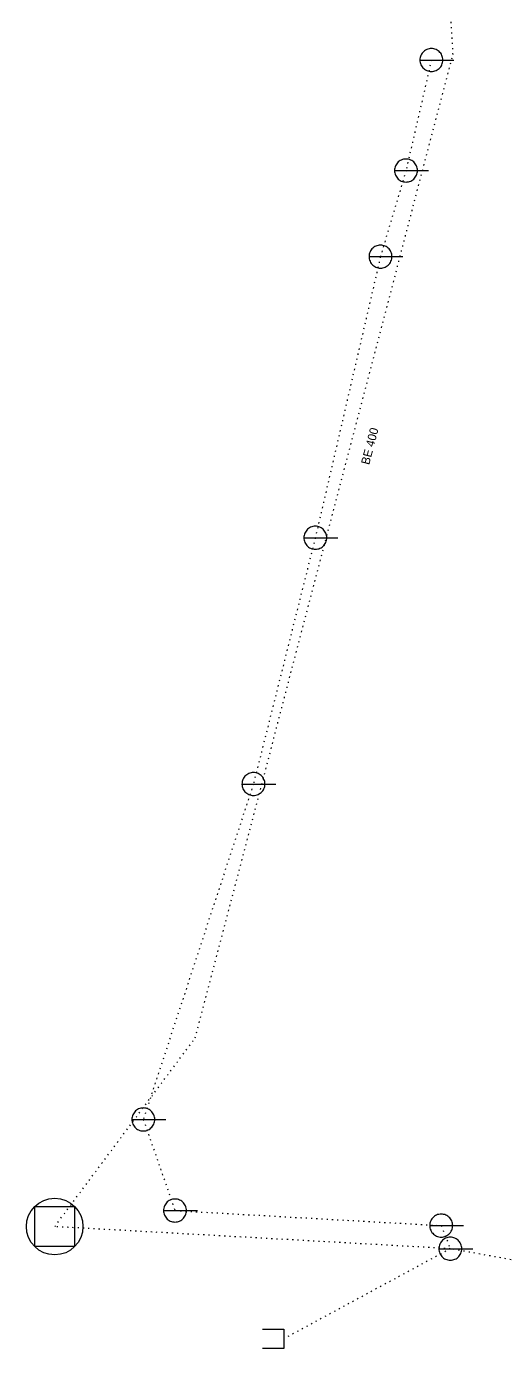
# Model space of a CAD drawing. Extents: x -688177 to -687620, y -1056713 to -1056287.
# Drawn here: x -688109.2 to -688067.1, y -1056697.7 to -1056581.7 of the extents above; entities that cross this region are included whole.
import ezdxf

# ---------------------------------------------------------------- set-up
doc = ezdxf.new("R2010")
doc.units = 0
doc.header["$LTSCALE"] = 0.3
doc.linetypes.add('DOTTED', pattern=[1.5, 0.3, -1.2])
for name, color, linetype, lineweight in [('12', 7, 'Continuous', 13), ('41', 7, 'DOTTED', 13), ('46', 7, 'DOTTED', 13)]:
    doc.layers.add(name, color=color, linetype=linetype, lineweight=lineweight)
doc.layers.add('18', color=7, linetype='Continuous')

msp = doc.modelspace()

# ---------------------------------------------------------------- linework, layer by layer
at = {"layer": '12'}
for p, q in [((-688074.648, -1056584.68), (-688071.672, -1056584.68)), ((-688076.878, -1056594.37), (-688073.902, -1056594.37)), ((-688079.118, -1056601.92), (-688076.142, -1056601.92)), ((-688084.838, -1056626.58), (-688081.862, -1056626.58)), ((-688090.268, -1056648.18), (-688087.292, -1056648.18)), ((-688099.938, -1056677.6), (-688096.962, -1056677.6)), ((-688097.158, -1056685.59), (-688094.182, -1056685.59)), ((-688073.788, -1056686.91), (-688070.812, -1056686.91)), ((-688072.988, -1056688.94), (-688070.012, -1056688.94)), ((-688086.607, -1056696.84), (-688086.593, -1056696.84))]:
    msp.add_line(p, q, dxfattribs=at)
for points in [[(-688073.64, -1056583.672), (-688073.745, -1056583.678), (-688073.849, -1056583.694), (-688073.951, -1056583.722), (-688074.05, -1056583.76), (-688074.144, -1056583.807), (-688074.232, -1056583.865), (-688074.314, -1056583.931), (-688074.389, -1056584.006), (-688074.455, -1056584.088), (-688074.513, -1056584.176), (-688074.56, -1056584.27), (-688074.598, -1056584.369), (-688074.626, -1056584.471), (-688074.642, -1056584.575), (-688074.648, -1056584.68), (-688074.642, -1056584.785), (-688074.626, -1056584.89), (-688074.598, -1056584.992), (-688074.56, -1056585.09), (-688074.513, -1056585.184), (-688074.455, -1056585.273), (-688074.389, -1056585.355), (-688074.314, -1056585.429), (-688074.232, -1056585.495), (-688074.144, -1056585.553), (-688074.05, -1056585.601), (-688073.951, -1056585.639), (-688073.849, -1056585.666), (-688073.745, -1056585.682), (-688073.64, -1056585.688), (-688073.535, -1056585.682), (-688073.43, -1056585.666), (-688073.328, -1056585.639), (-688073.23, -1056585.601), (-688073.136, -1056585.553), (-688073.047, -1056585.495), (-688072.965, -1056585.429), (-688072.891, -1056585.355), (-688072.825, -1056585.273), (-688072.767, -1056585.184), (-688072.719, -1056585.09), (-688072.681, -1056584.992), (-688072.654, -1056584.89), (-688072.638, -1056584.785), (-688072.632, -1056584.68), (-688072.638, -1056584.575), (-688072.654, -1056584.471), (-688072.681, -1056584.369), (-688072.719, -1056584.27), (-688072.767, -1056584.176), (-688072.825, -1056584.088), (-688072.891, -1056584.006), (-688072.965, -1056583.931), (-688073.047, -1056583.865), (-688073.136, -1056583.807), (-688073.23, -1056583.76), (-688073.328, -1056583.722), (-688073.43, -1056583.694), (-688073.535, -1056583.678)], [(-688075.87, -1056593.362), (-688075.975, -1056593.368), (-688076.079, -1056593.384), (-688076.181, -1056593.412), (-688076.28, -1056593.45), (-688076.374, -1056593.497), (-688076.462, -1056593.555), (-688076.544, -1056593.621), (-688076.619, -1056593.696), (-688076.685, -1056593.778), (-688076.743, -1056593.866), (-688076.79, -1056593.96), (-688076.828, -1056594.059), (-688076.856, -1056594.161), (-688076.872, -1056594.265), (-688076.878, -1056594.37), (-688076.872, -1056594.475), (-688076.856, -1056594.58), (-688076.828, -1056594.682), (-688076.79, -1056594.78), (-688076.743, -1056594.874), (-688076.685, -1056594.963), (-688076.619, -1056595.045), (-688076.544, -1056595.119), (-688076.462, -1056595.185), (-688076.374, -1056595.243), (-688076.28, -1056595.291), (-688076.181, -1056595.329), (-688076.079, -1056595.356), (-688075.975, -1056595.372), (-688075.87, -1056595.378), (-688075.765, -1056595.372), (-688075.66, -1056595.356), (-688075.558, -1056595.329), (-688075.46, -1056595.291), (-688075.366, -1056595.243), (-688075.277, -1056595.185), (-688075.195, -1056595.119), (-688075.121, -1056595.045), (-688075.055, -1056594.963), (-688074.997, -1056594.874), (-688074.949, -1056594.78), (-688074.911, -1056594.682), (-688074.884, -1056594.58), (-688074.868, -1056594.475), (-688074.862, -1056594.37), (-688074.868, -1056594.265), (-688074.884, -1056594.161), (-688074.911, -1056594.059), (-688074.949, -1056593.96), (-688074.997, -1056593.866), (-688075.055, -1056593.778), (-688075.121, -1056593.696), (-688075.195, -1056593.621), (-688075.277, -1056593.555), (-688075.366, -1056593.497), (-688075.46, -1056593.45), (-688075.558, -1056593.412), (-688075.66, -1056593.384), (-688075.765, -1056593.368)], [(-688078.11, -1056600.912), (-688078.215, -1056600.918), (-688078.319, -1056600.934), (-688078.421, -1056600.962), (-688078.52, -1056601), (-688078.614, -1056601.047), (-688078.702, -1056601.105), (-688078.784, -1056601.171), (-688078.859, -1056601.246), (-688078.925, -1056601.328), (-688078.983, -1056601.416), (-688079.03, -1056601.51), (-688079.068, -1056601.609), (-688079.096, -1056601.711), (-688079.112, -1056601.815), (-688079.118, -1056601.92), (-688079.112, -1056602.025), (-688079.096, -1056602.13), (-688079.068, -1056602.232), (-688079.03, -1056602.33), (-688078.983, -1056602.424), (-688078.925, -1056602.513), (-688078.859, -1056602.595), (-688078.784, -1056602.669), (-688078.702, -1056602.735), (-688078.614, -1056602.793), (-688078.52, -1056602.841), (-688078.421, -1056602.879), (-688078.319, -1056602.906), (-688078.215, -1056602.922), (-688078.11, -1056602.928), (-688078.005, -1056602.922), (-688077.9, -1056602.906), (-688077.798, -1056602.879), (-688077.7, -1056602.841), (-688077.606, -1056602.793), (-688077.517, -1056602.735), (-688077.435, -1056602.669), (-688077.361, -1056602.595), (-688077.295, -1056602.513), (-688077.237, -1056602.424), (-688077.189, -1056602.33), (-688077.151, -1056602.232), (-688077.124, -1056602.13), (-688077.108, -1056602.025), (-688077.102, -1056601.92), (-688077.108, -1056601.815), (-688077.124, -1056601.711), (-688077.151, -1056601.609), (-688077.189, -1056601.51), (-688077.237, -1056601.416), (-688077.295, -1056601.328), (-688077.361, -1056601.246), (-688077.435, -1056601.171), (-688077.517, -1056601.105), (-688077.606, -1056601.047), (-688077.7, -1056601), (-688077.798, -1056600.962), (-688077.9, -1056600.934), (-688078.005, -1056600.918)], [(-688083.83, -1056625.572), (-688083.935, -1056625.578), (-688084.039, -1056625.594), (-688084.141, -1056625.622), (-688084.24, -1056625.66), (-688084.334, -1056625.707), (-688084.422, -1056625.765), (-688084.504, -1056625.831), (-688084.579, -1056625.906), (-688084.645, -1056625.988), (-688084.703, -1056626.076), (-688084.75, -1056626.17), (-688084.788, -1056626.269), (-688084.816, -1056626.371), (-688084.832, -1056626.475), (-688084.838, -1056626.58), (-688084.832, -1056626.685), (-688084.816, -1056626.79), (-688084.788, -1056626.892), (-688084.75, -1056626.99), (-688084.703, -1056627.084), (-688084.645, -1056627.173), (-688084.579, -1056627.255), (-688084.504, -1056627.329), (-688084.422, -1056627.395), (-688084.334, -1056627.453), (-688084.24, -1056627.501), (-688084.141, -1056627.539), (-688084.039, -1056627.566), (-688083.935, -1056627.582), (-688083.83, -1056627.588), (-688083.725, -1056627.582), (-688083.62, -1056627.566), (-688083.518, -1056627.539), (-688083.42, -1056627.501), (-688083.326, -1056627.453), (-688083.237, -1056627.395), (-688083.155, -1056627.329), (-688083.081, -1056627.255), (-688083.015, -1056627.173), (-688082.957, -1056627.084), (-688082.909, -1056626.99), (-688082.871, -1056626.892), (-688082.844, -1056626.79), (-688082.828, -1056626.685), (-688082.822, -1056626.58), (-688082.828, -1056626.475), (-688082.844, -1056626.371), (-688082.871, -1056626.269), (-688082.909, -1056626.17), (-688082.957, -1056626.076), (-688083.015, -1056625.988), (-688083.081, -1056625.906), (-688083.155, -1056625.831), (-688083.237, -1056625.765), (-688083.326, -1056625.707), (-688083.42, -1056625.66), (-688083.518, -1056625.622), (-688083.62, -1056625.594), (-688083.725, -1056625.578)], [(-688089.26, -1056647.172), (-688089.365, -1056647.178), (-688089.469, -1056647.194), (-688089.571, -1056647.222), (-688089.67, -1056647.26), (-688089.764, -1056647.307), (-688089.852, -1056647.365), (-688089.934, -1056647.431), (-688090.009, -1056647.506), (-688090.075, -1056647.588), (-688090.133, -1056647.676), (-688090.18, -1056647.77), (-688090.218, -1056647.869), (-688090.246, -1056647.971), (-688090.262, -1056648.075), (-688090.268, -1056648.18), (-688090.262, -1056648.285), (-688090.246, -1056648.39), (-688090.218, -1056648.492), (-688090.18, -1056648.59), (-688090.133, -1056648.684), (-688090.075, -1056648.773), (-688090.009, -1056648.855), (-688089.934, -1056648.929), (-688089.852, -1056648.995), (-688089.764, -1056649.053), (-688089.67, -1056649.101), (-688089.571, -1056649.139), (-688089.469, -1056649.166), (-688089.365, -1056649.182), (-688089.26, -1056649.188), (-688089.155, -1056649.182), (-688089.05, -1056649.166), (-688088.948, -1056649.139), (-688088.85, -1056649.101), (-688088.756, -1056649.053), (-688088.667, -1056648.995), (-688088.585, -1056648.929), (-688088.511, -1056648.855), (-688088.445, -1056648.773), (-688088.387, -1056648.684), (-688088.339, -1056648.59), (-688088.301, -1056648.492), (-688088.274, -1056648.39), (-688088.258, -1056648.285), (-688088.252, -1056648.18), (-688088.258, -1056648.075), (-688088.274, -1056647.971), (-688088.301, -1056647.869), (-688088.339, -1056647.77), (-688088.387, -1056647.676), (-688088.445, -1056647.588), (-688088.511, -1056647.506), (-688088.585, -1056647.431), (-688088.667, -1056647.365), (-688088.756, -1056647.307), (-688088.85, -1056647.26), (-688088.948, -1056647.222), (-688089.05, -1056647.194), (-688089.155, -1056647.178)], [(-688098.93, -1056676.592), (-688099.035, -1056676.598), (-688099.139, -1056676.614), (-688099.241, -1056676.642), (-688099.34, -1056676.68), (-688099.434, -1056676.727), (-688099.522, -1056676.785), (-688099.604, -1056676.851), (-688099.679, -1056676.926), (-688099.745, -1056677.008), (-688099.803, -1056677.096), (-688099.85, -1056677.19), (-688099.888, -1056677.289), (-688099.916, -1056677.391), (-688099.932, -1056677.495), (-688099.938, -1056677.6), (-688099.932, -1056677.705), (-688099.916, -1056677.81), (-688099.888, -1056677.912), (-688099.85, -1056678.01), (-688099.803, -1056678.104), (-688099.745, -1056678.193), (-688099.679, -1056678.275), (-688099.604, -1056678.349), (-688099.522, -1056678.415), (-688099.434, -1056678.473), (-688099.34, -1056678.521), (-688099.241, -1056678.559), (-688099.139, -1056678.586), (-688099.035, -1056678.602), (-688098.93, -1056678.608), (-688098.825, -1056678.602), (-688098.72, -1056678.586), (-688098.618, -1056678.559), (-688098.52, -1056678.521), (-688098.426, -1056678.473), (-688098.337, -1056678.415), (-688098.255, -1056678.349), (-688098.181, -1056678.275), (-688098.115, -1056678.193), (-688098.057, -1056678.104), (-688098.009, -1056678.01), (-688097.971, -1056677.912), (-688097.944, -1056677.81), (-688097.928, -1056677.705), (-688097.922, -1056677.6), (-688097.928, -1056677.495), (-688097.944, -1056677.391), (-688097.971, -1056677.289), (-688098.009, -1056677.19), (-688098.057, -1056677.096), (-688098.115, -1056677.008), (-688098.181, -1056676.926), (-688098.255, -1056676.851), (-688098.337, -1056676.785), (-688098.426, -1056676.727), (-688098.52, -1056676.68), (-688098.618, -1056676.642), (-688098.72, -1056676.614), (-688098.825, -1056676.598)], [(-688096.15, -1056684.582), (-688096.255, -1056684.588), (-688096.359, -1056684.604), (-688096.461, -1056684.632), (-688096.56, -1056684.67), (-688096.654, -1056684.717), (-688096.742, -1056684.775), (-688096.824, -1056684.841), (-688096.899, -1056684.916), (-688096.965, -1056684.998), (-688097.023, -1056685.086), (-688097.07, -1056685.18), (-688097.108, -1056685.279), (-688097.136, -1056685.381), (-688097.152, -1056685.485), (-688097.158, -1056685.59), (-688097.152, -1056685.695), (-688097.136, -1056685.8), (-688097.108, -1056685.902), (-688097.07, -1056686), (-688097.023, -1056686.094), (-688096.965, -1056686.183), (-688096.899, -1056686.265), (-688096.824, -1056686.339), (-688096.742, -1056686.405), (-688096.654, -1056686.463), (-688096.56, -1056686.511), (-688096.461, -1056686.549), (-688096.359, -1056686.576), (-688096.255, -1056686.592), (-688096.15, -1056686.598), (-688096.045, -1056686.592), (-688095.94, -1056686.576), (-688095.838, -1056686.549), (-688095.74, -1056686.511), (-688095.646, -1056686.463), (-688095.557, -1056686.405), (-688095.475, -1056686.339), (-688095.401, -1056686.265), (-688095.335, -1056686.183), (-688095.277, -1056686.094), (-688095.229, -1056686), (-688095.191, -1056685.902), (-688095.164, -1056685.8), (-688095.148, -1056685.695), (-688095.142, -1056685.59), (-688095.148, -1056685.485), (-688095.164, -1056685.381), (-688095.191, -1056685.279), (-688095.229, -1056685.18), (-688095.277, -1056685.086), (-688095.335, -1056684.998), (-688095.401, -1056684.916), (-688095.475, -1056684.841), (-688095.557, -1056684.775), (-688095.646, -1056684.717), (-688095.74, -1056684.67), (-688095.838, -1056684.632), (-688095.94, -1056684.604), (-688096.045, -1056684.588)], [(-688108.464, -1056685.246), (-688104.956, -1056685.246), (-688104.956, -1056688.754), (-688108.464, -1056688.754)], [(-688072.78, -1056685.902), (-688072.885, -1056685.908), (-688072.989, -1056685.924), (-688073.091, -1056685.952), (-688073.19, -1056685.99), (-688073.284, -1056686.037), (-688073.372, -1056686.095), (-688073.454, -1056686.161), (-688073.529, -1056686.236), (-688073.595, -1056686.318), (-688073.653, -1056686.406), (-688073.7, -1056686.5), (-688073.738, -1056686.599), (-688073.766, -1056686.701), (-688073.782, -1056686.805), (-688073.788, -1056686.91), (-688073.782, -1056687.015), (-688073.766, -1056687.12), (-688073.738, -1056687.222), (-688073.7, -1056687.32), (-688073.653, -1056687.414), (-688073.595, -1056687.503), (-688073.529, -1056687.585), (-688073.454, -1056687.659), (-688073.372, -1056687.725), (-688073.284, -1056687.783), (-688073.19, -1056687.831), (-688073.091, -1056687.869), (-688072.989, -1056687.896), (-688072.885, -1056687.912), (-688072.78, -1056687.918), (-688072.675, -1056687.912), (-688072.57, -1056687.896), (-688072.468, -1056687.869), (-688072.37, -1056687.831), (-688072.276, -1056687.783), (-688072.187, -1056687.725), (-688072.105, -1056687.659), (-688072.031, -1056687.585), (-688071.965, -1056687.503), (-688071.907, -1056687.414), (-688071.859, -1056687.32), (-688071.821, -1056687.222), (-688071.794, -1056687.12), (-688071.778, -1056687.015), (-688071.772, -1056686.91), (-688071.778, -1056686.805), (-688071.794, -1056686.701), (-688071.821, -1056686.599), (-688071.859, -1056686.5), (-688071.907, -1056686.406), (-688071.965, -1056686.318), (-688072.031, -1056686.236), (-688072.105, -1056686.161), (-688072.187, -1056686.095), (-688072.276, -1056686.037), (-688072.37, -1056685.99), (-688072.468, -1056685.952), (-688072.57, -1056685.924), (-688072.675, -1056685.908)], [(-688071.98, -1056687.932), (-688072.085, -1056687.938), (-688072.189, -1056687.954), (-688072.291, -1056687.982), (-688072.39, -1056688.02), (-688072.484, -1056688.067), (-688072.572, -1056688.125), (-688072.654, -1056688.191), (-688072.729, -1056688.266), (-688072.795, -1056688.348), (-688072.853, -1056688.436), (-688072.9, -1056688.53), (-688072.938, -1056688.629), (-688072.966, -1056688.731), (-688072.982, -1056688.835), (-688072.988, -1056688.94), (-688072.982, -1056689.045), (-688072.966, -1056689.15), (-688072.938, -1056689.252), (-688072.9, -1056689.35), (-688072.853, -1056689.444), (-688072.795, -1056689.533), (-688072.729, -1056689.615), (-688072.654, -1056689.689), (-688072.572, -1056689.755), (-688072.484, -1056689.813), (-688072.39, -1056689.861), (-688072.291, -1056689.899), (-688072.189, -1056689.926), (-688072.085, -1056689.942), (-688071.98, -1056689.948), (-688071.875, -1056689.942), (-688071.77, -1056689.926), (-688071.668, -1056689.899), (-688071.57, -1056689.861), (-688071.476, -1056689.813), (-688071.387, -1056689.755), (-688071.305, -1056689.689), (-688071.231, -1056689.615), (-688071.165, -1056689.533), (-688071.107, -1056689.444), (-688071.059, -1056689.35), (-688071.021, -1056689.252), (-688070.994, -1056689.15), (-688070.978, -1056689.045), (-688070.972, -1056688.94), (-688070.978, -1056688.835), (-688070.994, -1056688.731), (-688071.021, -1056688.629), (-688071.059, -1056688.53), (-688071.107, -1056688.436), (-688071.165, -1056688.348), (-688071.231, -1056688.266), (-688071.305, -1056688.191), (-688071.387, -1056688.125), (-688071.476, -1056688.067), (-688071.57, -1056688.02), (-688071.668, -1056687.982), (-688071.77, -1056687.954), (-688071.875, -1056687.938)]]:
    msp.add_lwpolyline(points, close=True, dxfattribs=at)
msp.add_lwpolyline([(-688088.474, -1056695.984), (-688086.6, -1056695.984), (-688086.6, -1056697.696), (-688088.474, -1056697.696)], dxfattribs=at)
msp.add_circle((-688106.71, -1056687), 2.481, dxfattribs=at)
at = {"layer": '41'}
msp.add_lwpolyline([(-688040.3, -1056692.5), (-688055.33, -1056691.94), (-688071.98, -1056688.94)], dxfattribs=at)
at = {"layer": '46'}
for q in [(-688106.71, -1056687), (-688086.51, -1056696.8)]:
    msp.add_line((-688071.98, -1056688.94), q, dxfattribs=at)
for points in [[(-688106.71, -1056687), (-688094.37, -1056670.45), (-688071.74, -1056584.19), (-688072.49, -1056571.56)], [(-688073.64, -1056584.68), (-688075.87, -1056594.37), (-688078.11, -1056601.92), (-688083.83, -1056626.58), (-688089.26, -1056648.18), (-688098.93, -1056677.6), (-688096.15, -1056685.59), (-688072.78, -1056686.91), (-688071.98, -1056688.94)]]:
    msp.add_lwpolyline(points, dxfattribs=at)

# ---------------------------------------------------------------- texts
at = {"layer": '18'}
msp.add_text('BE 400', height=0.75, rotation=75.3, dxfattribs=at).set_placement((-688079.106, -1056620.228))

doc.saveas('drawing.dxf')
